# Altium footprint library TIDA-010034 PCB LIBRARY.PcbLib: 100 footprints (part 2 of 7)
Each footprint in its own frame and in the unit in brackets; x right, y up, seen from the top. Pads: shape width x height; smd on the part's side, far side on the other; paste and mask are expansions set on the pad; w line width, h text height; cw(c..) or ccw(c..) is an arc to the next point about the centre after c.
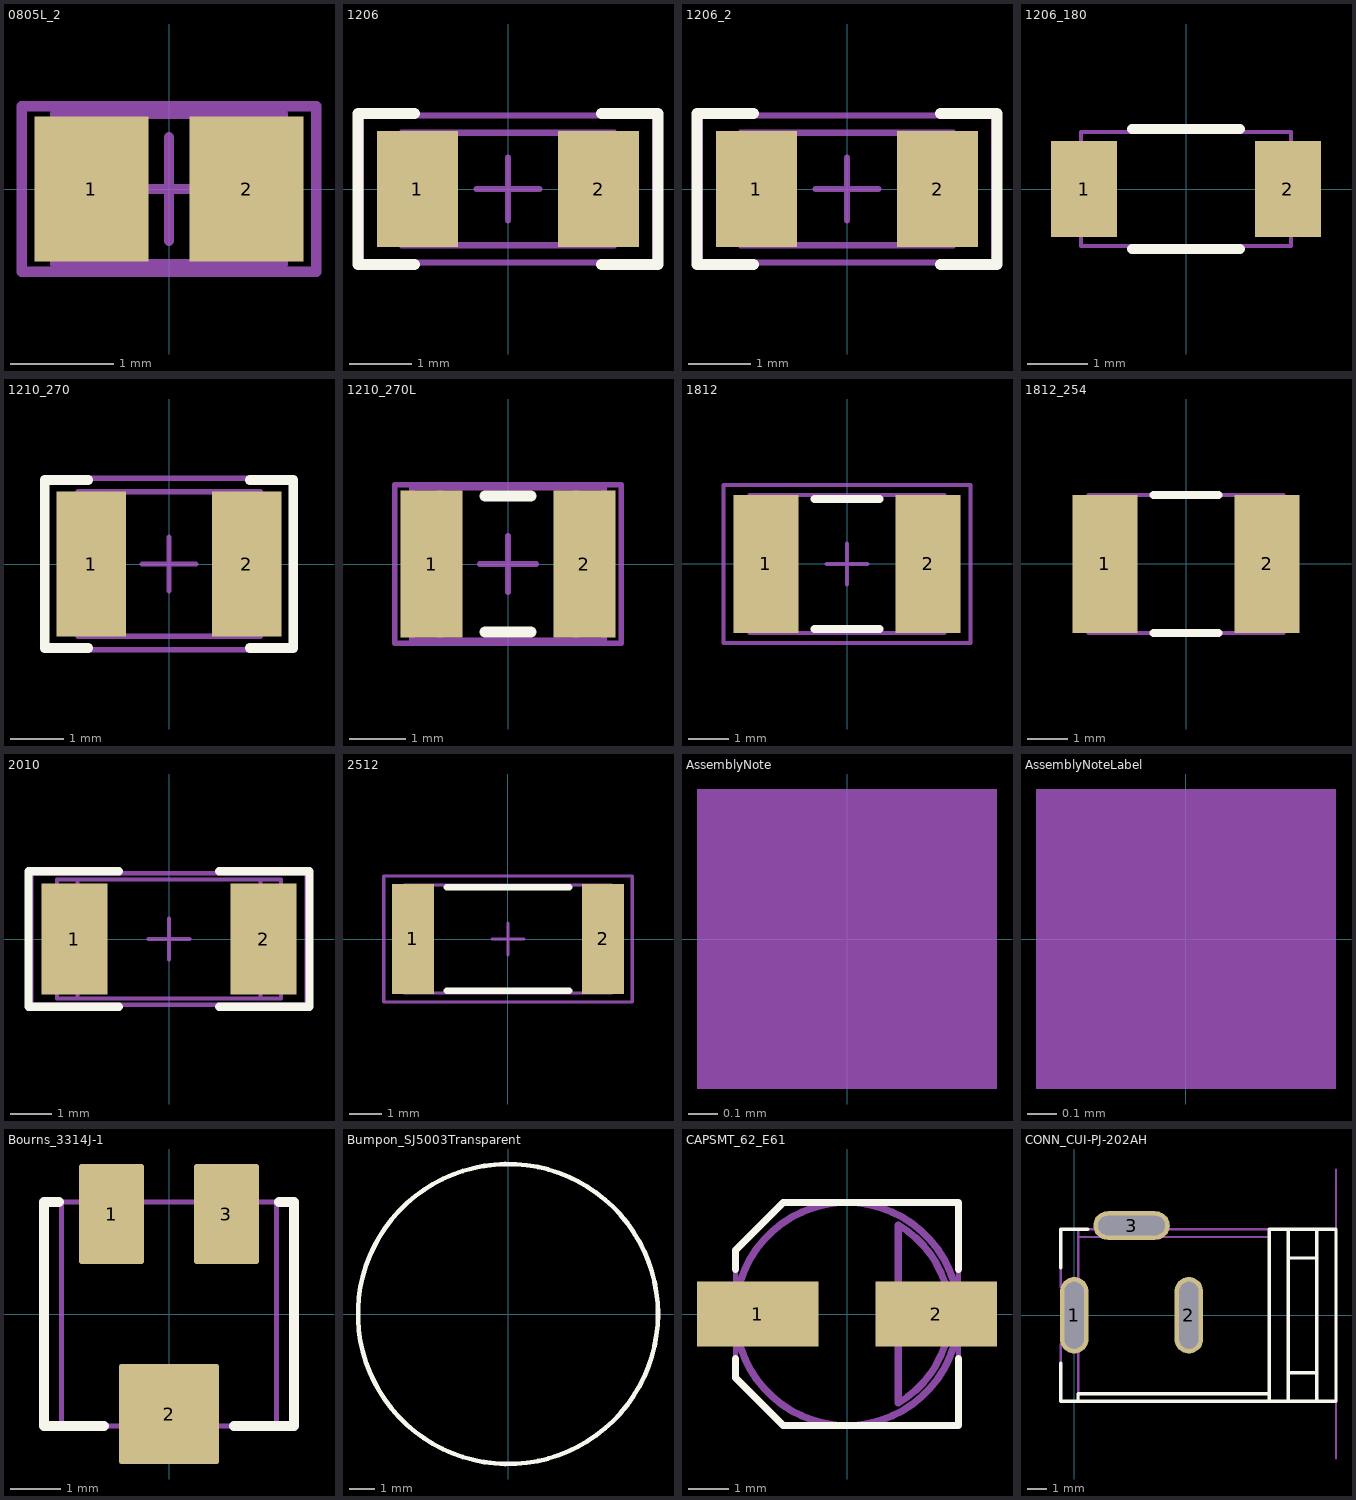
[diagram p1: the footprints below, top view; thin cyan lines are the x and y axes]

## 0805L_2 [mm]
pads (2):
  rect 1.1x1.4 smd: 1(-0.75,0) 2(0.75,0)
Mechanical 5:
  lines w0.1: -1.425,-0.8 -1.425,0.8 1.425,0.8 1.425,-0.8 -1.425,-0.8
  text ".Designator" at -1.2,-0.325 h0.64
Mechanical 13:
  lines w0.1: -0.65,-0.725 -0.65,0.725 ; 0.65,-0.725 0.65,0.725 ; -1.1,-0.725 1.1,-0.725 1.1,0.725 -1.1,0.725 -1.1,-0.725
Mechanical 15:
  lines w0.1: -0.5,0 0.5,0 ; 0,-0.5 0,0.5 ; -1.425,-0.8 1.425,-0.8 1.425,0.8 -1.425,0.8 -1.425,-0.8
3D body: height 1.45, standoff 0, extent -1.099,-0.724 -0.651,0.724
3D body: height 1.45, standoff 0, extent -0.649,-0.724 0.649,0.724
3D body: height 1.45, standoff 0, extent 0.651,-0.724 1.099,0.724

## 1206 [mm] "1206 from SM-752 data"
height 1.35
pads (2):
  rect 1.3x1.85 smd: 1(-1.45,0) 2(1.45,0)
Top Overlay:
  lines w0.178: -1.5,-1.21 -2.4,-1.21 -2.4,1.21 -1.5,1.21 ; 1.5,-1.21 2.4,-1.21 2.4,1.21 1.5,1.21
Mechanical 5:
  lines w0.1: -1.7,-0.9 1.7,-0.9 1.7,0.9 -1.7,0.9 -1.7,-0.9
  text ".Designator" at -1.475,-0.4 h0.81
Mechanical 13:
  lines w0.1: -1.2,-0.9 -1.2,0.9 ; 1.2,-0.9 1.2,0.9 ; -1.7,-0.9 1.7,-0.9 1.7,0.9 -1.7,0.9 -1.7,-0.9
Mechanical 15:
  lines w0.1: -0.5,0 0.5,0 ; 0,-0.5 0,0.5 ; -2.35,-1.175 2.35,-1.175 2.35,1.175 -2.35,1.175 -2.35,-1.175
3D body: height 1.35, standoff 0, extent -1.699,-0.899 -1.201,0.899
3D body: height 1.35, standoff 0, extent -1.199,-0.899 1.199,0.899
3D body: height 1.35, standoff 0, extent 1.201,-0.899 1.699,0.899

## 1206_2 [mm]
pads (2):
  rect 1.3x1.85 smd: 1(-1.45,0) 2(1.45,0)
Top Overlay:
  lines w0.178: -1.5,-1.21 -2.4,-1.21 -2.4,1.21 -1.5,1.21 ; 1.5,-1.21 2.4,-1.21 2.4,1.21 1.5,1.21
Mechanical 5:
  lines w0.1: -1.7,-0.9 1.7,-0.9 1.7,0.9 -1.7,0.9 -1.7,-0.9
  text ".Designator" at -1.475,-0.4 h0.81
Mechanical 13:
  lines w0.1: -1.2,-0.9 -1.2,0.9 ; 1.2,-0.9 1.2,0.9 ; -1.7,-0.9 1.7,-0.9 1.7,0.9 -1.7,0.9 -1.7,-0.9
Mechanical 15:
  lines w0.1: -0.5,0 0.5,0 ; 0,-0.5 0,0.5 ; -2.35,-1.175 2.35,-1.175 2.35,1.175 -2.35,1.175 -2.35,-1.175
3D body: height 1.35, standoff 0, extent -1.699,-0.899 -1.201,0.899
3D body: height 1.35, standoff 0, extent -1.199,-0.899 1.199,0.899
3D body: height 1.35, standoff 0, extent 1.201,-0.899 1.699,0.899

## 1206_180 [mm] "1206_180"
height 1.8
pads (2):
  rect 1.1x1.6 smd: 1(-1.7,0) 2(1.7,0)
Top Overlay:
  lines w0.17: -0.9,-1 0.9,-1 ; -0.9,1 0.9,1
Mechanical 5:
  lines w0.07: -1.75,-0.95 -1.75,0.95 1.75,0.95 1.75,-0.95 -1.75,-0.95
  text ".Designator" at -1.5,-0.4 h0.81
3D body: height 1.8, standoff 0, extent 1.301,-0.949 1.749,0.949
3D body: height 1.8, standoff 0, extent -1.299,-0.949 1.299,0.949
3D body: height 1.8, standoff 0, extent -1.749,-0.949 -1.301,0.949

## 1210_270 [mm] "1210"
height 2.7
pads (2):
  rect 1.3x2.7 smd: 1(-1.45,0) 2(1.45,0)
Top Overlay:
  lines w0.178: -1.511,-1.568 -2.316,-1.568 -2.316,1.568 -1.511,1.568 ; 1.511,-1.568 2.316,-1.568 2.316,1.568 1.511,1.568
Mechanical 5:
  lines w0.1: -1.7,-1.35 1.7,-1.35 1.7,1.35 -1.7,1.35 -1.7,-1.35
  text ".Designator" at -1.4,-0.375 h0.76
Mechanical 13:
  lines w0.1: -1.2,-1.35 -1.2,1.35 ; 1.2,-1.35 1.2,1.35 ; -1.7,-1.35 -1.7,1.35 1.7,1.35 1.7,-1.35 -1.7,-1.35
Mechanical 15:
  lines w0.1: -0.5,0 0.5,0 ; 0,-0.5 0,0.5 ; -2.35,-1.6 -2.35,1.6 2.35,1.6 2.35,-1.6 -2.35,-1.6
3D body: height 2.7, standoff 0, extent -1.699,-1.349 -1.201,1.349
3D body: height 2.7, standoff 0, extent -1.199,-1.349 1.199,1.349
3D body: height 2.7, standoff 0, extent 1.201,-1.349 1.699,1.349

## 1210_270L [mm] "1210"
height 2.7
pads (2):
  rect 1.1x2.6 smd: 1(-1.35,0) 2(1.35,0)
Top Overlay:
  lines w0.2: -0.4,-1.2 0.4,-1.2 ; -0.4,1.2 0.4,1.2
Mechanical 5:
  lines w0.1: -1.7,-1.35 1.7,-1.35 1.7,1.35 -1.7,1.35 -1.7,-1.35
  text ".Designator" at -1.4,-0.375 h0.76
Mechanical 13:
  lines w0.1: -1.2,-1.35 -1.2,1.35 ; 1.2,-1.35 1.2,1.35 ; -1.7,-1.35 1.7,-1.35 1.7,1.35 -1.7,1.35 -1.7,-1.35
Mechanical 15:
  lines w0.1: -0.5,0 0.5,0 ; 0,-0.5 0,0.5 ; -2,-1.4 -2,1.4 2,1.4 2,-1.4 -2,-1.4
3D body: height 2.7, standoff 0, extent 1.201,-1.349 1.699,1.349
3D body: height 2.7, standoff 0, extent -1.199,-1.349 1.199,1.349
3D body: height 2.7, standoff 0, extent -1.699,-1.349 -1.201,1.349

## 1812 [mm]
height 1.35
pads (2):
  rect 1.6x3.4 smd: 1(-2,0) 2(2,0)
Top Overlay:
  lines w0.2: -0.8,-1.6 0.8,-1.6 ; -0.8,1.6 0.8,1.6
Mechanical 5:
  lines w0.1: -2.4,-1.7 2.4,-1.7 2.4,1.7 -2.4,1.7 -2.4,-1.7
  text ".Designator" at -1.875,-0.5 h1.02
Mechanical 13:
  lines w0.1: -1.9,-1.7 -1.9,1.7 ; 1.9,-1.7 1.9,1.7 ; -2.4,-1.7 -2.4,1.7 2.4,1.7 2.4,-1.7 -2.4,-1.7
Mechanical 15:
  lines w0.1: -0.5,0 0.5,0 ; 0,-0.5 0,0.5 ; -3.05,-1.95 -3.05,1.95 3.05,1.95 3.05,-1.95 -3.05,-1.95
3D body: height 1.35, standoff 0, extent -2.399,-1.699 -1.901,1.699
3D body: height 1.35, standoff 0, extent -1.899,-1.699 1.899,1.699
3D body: height 1.35, standoff 0, extent 1.901,-1.699 2.399,1.699

## 1812_254 [mm] "SMD, 2-Leads, Body 4.8x3.4mm"
height 2.54
pads (2):
  rect 1.6x3.4 smd: 1(-2,0) 2(2,0)
Top Overlay:
  lines w0.2: -0.8,-1.7 0.8,-1.7 ; -0.8,1.7 0.8,1.7
Mechanical 5:
  lines w0.1: -1.9,-1.7 -1.9,1.7 ; 1.9,-1.7 1.9,1.7 ; -2.4,-1.7 2.4,-1.7 2.4,1.7 -2.4,1.7 -2.4,-1.7
  text ".Designator" at -1.875,-0.5 h1.02
3D body: height 2.54, standoff 0, extent -2.399,-1.699 -1.901,1.699
3D body: height 2.54, standoff 0, extent -1.899,-1.699 1.899,1.699
3D body: height 2.54, standoff 0, extent 1.901,-1.699 2.399,1.699

## 2010 [mm] "Chip Capacitor, Body 5.08x2.54mm, IPC Medium Density"
height 1.66
pads (2):
  rect 1.6x2.7 smd: 1(-2.3,0) 2(2.3,0)
Top Overlay:
  lines w0.2: -1.219,-1.65 -3.419,-1.65 -3.419,1.65 -1.219,1.65 ; 1.219,-1.65 3.419,-1.65 3.419,1.65 1.219,1.65
Mechanical 5:
  lines w0.1: -2.73,-1.45 2.73,-1.45 2.73,1.45 -2.73,1.45 -2.73,-1.45
  text ".Designator" at -1.875,-0.5 h1.02
Mechanical 13:
  lines w0.1: -2.23,-1.45 -2.23,1.45 ; 2.23,-1.45 2.23,1.45 ; -2.73,-1.45 -2.73,1.45 2.73,1.45 2.73,-1.45 -2.73,-1.45
Mechanical 15:
  lines w0.1: -0.5,0 0.5,0 ; 0,-0.5 0,0.5 ; -3.35,-1.6 -3.35,1.6 3.35,1.6 3.35,-1.6 -3.35,-1.6
3D body: height 1.66, standoff 0, extent 2.231,-1.449 2.729,1.449
3D body: height 1.66, standoff 0, extent -2.229,-1.449 2.229,1.449
3D body: height 1.66, standoff 0, extent -2.729,-1.449 -2.231,1.449

## 2512 [mm] "Chip Resistor, Body 6.3x3.2mm, IPC Medium Density"
height 0.71
pads (2):
  rect 1.3x3.4 smd: 1(-2.95,0) 2(2.95,0)
Top Overlay:
  lines w0.2: -1.9,-1.6 1.9,-1.6 ; -1.9,1.6 1.9,1.6
Mechanical 5:
  lines w0.1: -3.225,-1.675 -3.225,1.675 3.225,1.675 3.225,-1.675 -3.225,-1.675
  text ".Designator" at -1.85,-0.5 h1.02
Mechanical 13:
  lines w0.1: -2.463,-1.675 -2.463,1.675 ; 2.463,-1.675 2.463,1.675 ; -3.225,-1.675 -3.225,1.675 3.225,1.675 3.225,-1.675 -3.225,-1.675
Mechanical 15:
  lines w0.1: -0.5,0 0.5,0 ; 0,-0.5 0,0.5 ; -3.85,-1.95 -3.85,1.95 3.85,1.95 3.85,-1.95 -3.85,-1.95
3D body: height 0.71, standoff 0, extent 2.464,-1.674 3.224,1.674
3D body: height 0.71, standoff 0, extent -2.462,-1.674 2.462,1.674
3D body: height 0.71, standoff 0, extent -3.224,-1.674 -2.464,1.674

## AssemblyNote [mm] "Assembly Note"
Mechanical 5:
  rectangle: -0.508,-0.508 0.508,0.508
  text ".Designator" at 29.083,5.461 h1.02
  text ".Comment" at 1.143,-0.508 h1.02

## AssemblyNoteLabel [mm] "Assembly Note for PCB Labels"
Mechanical 5:
  rectangle: -0.508,-0.508 0.508,0.508
  text ".Designator" at -4.191,-0.508 h1.02
  text "Install label in silkscreened box after final wash.  Text shall be 8 pt font.  Text shall be per the Label Table in the PDF schematic." at 1.143,-0.508 h1.02

## Bourns_3314J-1 [mm] "SMD, 3-Leads, Body 5x4.5mm"
height 2.8
pads (3):
  rrect8% 1.3x2 smd: 1(-1.15,2) 3(1.15,2)
  rrect5% 2x2 smd: 2(0,-2)
Top Overlay:
  lines w0.2: -2.2,2.235 -2.5,2.235 -2.5,-2.235 -1.3,-2.235 ; 1.3,-2.235 2.5,-2.235 2.5,2.235 2.2,2.235
Mechanical 5:
  lines w0.1: -1.575,2.25 -1.575,2.502 -0.965,2.502 -0.965,2.25 ; -0.305,-2.25 -0.305,-2.502 0.305,-2.502 0.305,-2.25 ; 0.965,2.25 0.965,2.502 1.575,2.502 1.575,2.25 ; -2.148,-2.235 -2.148,2.235 ; -2.148,-2.235 2.148,-2.235 ; -2.148,-2.235 -2.413,-2.235 -2.5,-2.235 -2.5,2.235 -2.413,2.235 -2.148,2.235 ; -2.148,2.235 2.148,2.235 ; 2.148,-2.235 2.148,2.235 ; 2.148,-2.235 2.413,-2.235 2.5,-2.235 2.5,2.235 2.413,2.235 2.148,2.235 ; -0.322,-1.472 cw(c-0.278,-1.447) -0.269,-1.397 ccw(c0,0) 0.269,-1.397 cw(c0.278,-1.447) 0.322,-1.472 0.044,-1.954 cw(c0,-1.929) -0.044,-1.954 -0.322,-1.472
  text ".Designator" at -1.2,-0.3 h1.3
3D body "3314J-1.stp": height 2.73, standoff 0, extent -2.5,-2.502 2.499,2.502

## Bumpon_SJ5003Transparent [mil] "3M Hemispherical Bumpon transparent"
height 200
pads (1):
  round 1 on Mech3: 0(0,0)
Top Overlay:
  circle w7: c0,0 r228.04
Mechanical 5:
  circle w5: c0,0 r228.04
  text ".Designator" at -60,-20 h40
3D body "3M_SJ5003Transparent.stp": height 196.82, standoff 0, extent -218.5,-218.5 218.51,218.51

## CAPSMT_62_E61 [mm] "5 x 5.8mm:  Chemi-Con E61"
height 6.1
pads (2):
  rect 3x1.6 smd: 1(-2.2,0) 2(2.2,0)
Top Overlay:
  lines w0.178: -2.75,-1.1 -2.75,-1.575 -1.575,-2.75 0,-2.75 2.75,-2.75 2.75,-1.1 ; -2.75,1.1 -2.75,1.575 -1.575,2.75 0,2.75 2.75,2.75 2.75,1.1
Mechanical 5:
  lines w0.127: -2.75,-1.575 -1.575,-2.75 0,-2.75 2.75,-2.75 2.75,2.75 0,2.75 -1.575,2.75 -2.75,1.575 -2.75,-1.575
  text ".Designator" at -1.524,-0.508 h1.02
Mechanical 13:
  circle w0.178: c0,0 r2.75
  lines w0.178: 1.266,-2.194 ccw(c0,0) 1.266,2.194 1.266,-2.194
3D body: height 6.1, standoff 6, extent 1.266,-2.194 2.533,2.194
3D body: height 6.1, standoff 1, extent -2.749,-2.749 2.749,2.749
3D body: height 1, standoff 0, extent -2.751,-2.751 2.751,2.751

## CONN_CUI-PJ-202AH [mm] "Conn_DC Jack"
height 11
pads (3):
  oval 1.5x4 hole 1 slot 3.5 at 90 deg: 1(0,0) 2(6,0)
  oval 4x1.5 hole 1 slot 3.5 at 0 deg: 3(3,4.7)
Top Overlay:
  lines w0.178: -0.7,-2.5 -0.7,-4.5 0.2,-4.5 ; -0.7,2.5 -0.7,4.5 0.2,4.5 0.7,4.5 ; 10.2,-4.1 0.2,-4.1 0.2,-4.5 ; 11.2,-3 12.7,-3 ; 11.2,3 12.7,3 ; 0.2,-4.5 10.2,-4.5 ; 10.2,-4.5 10.2,4.5 11.2,4.5 ; 10.2,-4.5 11.2,-4.5 ; 11.2,-4.5 12.7,-4.5 ; 11.2,-4.5 11.2,4.5 ; 11.2,4.5 12.7,4.5 ; 12.7,-4.5 13.7,-4.5 13.7,4.5 12.7,4.5 ; 12.7,-4.5 12.7,4.5
Mechanical 1:
  lines w0.127: 13.7,-7.48 13.7,7.62
Mechanical 5:
  lines w0.127: 0.2,-1.5 -0.2,-1.5 ; 0.2,1.5 -0.2,1.5 ; 1.75,4.5 1.75,4.9 4.25,4.9 4.25,4.5 ; 10.2,-4.1 0.2,-4.1 ; 10.2,4.1 0.2,4.1 ; 11.2,-3 12.7,-3 ; 11.2,3 12.7,3 ; -0.2,-1.5 -0.7,-1.5 -0.7,-4.5 0.2,-4.5 ; -0.2,-1.5 -0.2,1.5 ; -0.2,1.5 -0.7,1.5 -0.7,4.5 0.2,4.5 ; 0.2,-4.5 0.2,-4.1 ; 0.2,-4.5 10.2,-4.5 ; 0.2,-4.1 0.2,4.1 ; 0.2,4.1 0.2,4.5 ; 0.2,4.5 10.2,4.5 ; 10.2,-4.5 11.2,-4.5 ; 10.2,-4.5 10.2,4.5 ; 10.2,4.5 11.2,4.5 ; 11.2,-4.5 11.2,4.5 ; 11.2,-4.5 12.7,-4.5 ; 11.2,4.5 12.7,4.5 ; 12.7,-4.5 12.7,4.5 ; 12.7,-4.5 13.7,-4.5 13.7,4.5 12.7,4.5
  text ".Designator" at 1.4,-0.4 h1.02
3D body "PJ-202AH.stp": height 11.02, standoff -3.48, extent -0.7,-4.5 13.7,4.9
